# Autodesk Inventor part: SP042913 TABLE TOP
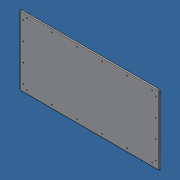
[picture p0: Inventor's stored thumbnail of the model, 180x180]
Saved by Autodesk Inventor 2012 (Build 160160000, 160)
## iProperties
Created: 2013-04
Part Number: SP042913 TABLE TOP
Material: High Density Polyethylene
Document SubType Name: Modeling
Designer: Admin
Density: 0.952 g/cm^3
Stock Number: SPECIFY MATERIAL
Mass: 20159.7 g
Surface Area: 34019 cm^2
Volume: 21176.1 cm^3
Author: Admin
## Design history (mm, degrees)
sketch "Sketch1"
  geometry: L1 (-914.4, 457.2)-(914.4, 457.2); L2 (914.4, 457.2)-(914.4, -457.2); L3 (914.4, -457.2)-(-914.4, -457.2); L4 (-914.4, -457.2)-(-914.4, 457.2); 3 further points
  constraints: 8 end point, 2 midpoint, 2 parallel, 1 horizontal, 1 horizontal alignment, 1 perpendicular, 1 vertical alignment
  dimensions: "d0" = 1828.8 distance of L1.start L1.end (= Width); "d1" = 914.4 distance of L3.end L1.start (= DEPTH)
extrude "Extrusion1" new body sketch "Sketch1" distance "d2" = 12.7 (= TABLE_TOP_THICKNESS); taper "d3" = 0 deg
fillet "Fillet1" dims "d4" = 15.2 (computed from TOP_OVERHANG)
fillet "Fillet2" dims "d5" = 6.35
sketch "Sketch2"
  geometry: L1 (-899.2, 457.2)-(899.2, 457.2) reference; L2 (914.4, 442)-(914.4, -442) reference; L3 (899.2, -457.2)-(-899.2, -457.2) reference; L4 (-914.4, -442)-(-914.4, 442) reference; A1 r 15.2 centre (-899.2, 442) between (-899.2, 457.2) and (-914.4, 442) reference; A2 r 15.2 centre (899.2, 442) between (914.4, 442) and (899.2, 457.2) reference; A3 r 15.2 centre (899.2, -442) between (899.2, -457.2) and (914.4, -442) reference; A4 r 15.2 centre (-899.2, -442) between (-914.4, -442) and (-899.2, -457.2) reference; 25 further points
  constraints: 14 horizontal alignment, 12 vertical alignment
  dimensions: "d6" = 47.9044 distance from line of point (-866.496, -361.95) L4 (computed from TOP_OVERHANG); "d10" = 95.25 distance from line of point (819.15, 409.296) L2 (= d12); "d12" = 95.25 distance from line of point (-866.496, -361.95) L3 (computed from TOP_OVERHANG); "d13" = 95.25 distance from line of point (-819.15, -409.296) L4 (= d12); "d14" = 47.9044 distance from line of point (-819.15, -409.296) L3 (= d6); "d15" = 47.9044 distance from line of point (819.15, 409.296) L1 (= d14); "d16" = 95.25 distance from line of point (866.496, 361.95) L1 (= d10); "d17" = 47.9044 distance from line of point (866.496, 361.95) L2 (= d15); "d18" = 1638.3 distance of point (819.15, -409.296) point (-819.15, -409.296) (derived); "d19" = 327.66 distance of point (-491.49, -409.296) point (-819.15, -409.296) (= 0.2 x d18); "d20" = 327.66 distance of point (-163.83, -409.296) point (-491.49, -409.296) (= d19); "d21" = 327.66 distance of point (163.83, -409.296) point (-163.83, -409.296) (= d20); "d22" = 327.66 distance of point (491.49, -409.296) point (163.83, -409.296) (= d21); "d23" = 723.9 distance of point (-866.496, 361.95) point (-866.496, -361.95) (derived); "d24" = 241.3 distance of point (-866.496, -120.65) point (-866.496, -361.95) (= 0.333333 x d23); "d25" = 241.3 distance of point (-866.496, 120.65) point (-866.496, -120.65) (= d24)
hole "Hole1" sketch "Sketch2" at (-866.496, -361.95), (-819.15, -409.296), (-866.496, -120.65), (-866.496, 120.65), (-866.496, 361.95), (-819.15, 409.296), (-491.49, 409.296), (-491.49, -409.296), (-163.83, -409.296), (-163.83, 409.296), (163.83, 409.296), (163.83, -409.296)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 diameter "d26" = 6.5; stored, may be unused: countersink angle "d30" = 90 deg, drill point angle "d32" = 118 deg; dims "d27" = 19.05, "d28" = 13.5, "d29" = 6.35, "d31" = 25.4
body "Solid1"
node "Projected Loop1"
other parameters: "Height" = 1066.8 [user parameter], "Width" = 1828.8 [user parameter; used in 1 equation term], "DEPTH" = 914.4 [user parameter; used in 1 equation term], "LOWER_INSET" = 203.2 [user parameter], "TABLE_TOP_THICKNESS" = 12.7 [user parameter; used in 1 equation term], "LEVELER_HEIGHT" = 44.45 [user parameter], "TOP_OVERHANG" = 25.4 [user parameter; used in 3 equation terms], "d8" = 47.9044 (= d6)
